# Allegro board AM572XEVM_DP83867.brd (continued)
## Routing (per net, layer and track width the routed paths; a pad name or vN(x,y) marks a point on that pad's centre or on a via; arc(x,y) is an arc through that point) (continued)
DDR2_D27: length 24.5
  TOP w0.12: U11.L28 55.72,38.01 54.86,38.86 54.49,38.86 54.38,38.76 54.38,38.33 54.28,38.23 54.13,38.23 54.02,38.33 54.02,38.76 53.92,38.86 53.77,38.86 53.66,38.76 53.66,38.33 53.56,38.23 53.41,38.23 53.3,38.33 53.3,38.76 53.2,38.86 53.05,38.86 52.95,38.76 52.95,38.33 52.84,38.23 52.69,38.23 52.59,38.33 52.59,38.76 52.48,38.86 52.33,38.86 52.23,38.76 52.23,38.33 52.12,38.23 51.97,38.23 51.87,38.33 51.87,38.76 51.76,38.86 51.61,38.86 51.51,38.76 51.51,38.33 51.4,38.23 51.25,38.23 51.15,38.33 51.15,38.76 51.04,38.86 50.55,38.86 49.78,38.1 49.78,35.69 48.51,34.42 43.17,34.42 43.05,34.3 43.05,33.13 U26.F7
DDR2_D28: length 24.2
  TOP w0.12: U11.M23 v2(60.19,38.41) ; v2(44.18,31.2) U26.F8
  INT_L3 w0.094: v2(60.19,38.41) 60.19,38.62 59.82,38.99 59.82,39.24 59.56,39.5 47.98,39.5 46.14,37.65 46.14,37.46 45.83,37.16 45.64,37.16 45.34,36.85 45.34,36.66 45.13,36.45 44.93,36.45 44.58,36.1 44.58,31.6 v2(44.18,31.2)
DDR2_D29: length 23.9
  TOP w0.12: v2(42.58,36) U26.H3 ; U11.M24 v2(59.39,38.41)
  BOTTOM w0.12: v2(59.39,38.41) 58.99,38.01 53.63,38.01 49.66,34.04 49.37,34.04 49.27,34.14 49.27,34.18 49.16,34.29 49.01,34.29 48.91,34.18 48.91,34.14 48.8,34.04 48.65,34.04 48.55,34.14 48.55,34.18 48.44,34.29 48.29,34.29 48.19,34.18 48.19,34.14 48.08,34.04 47.93,34.04 47.83,34.14 47.83,34.18 47.72,34.29 47.57,34.29 47.47,34.18 47.47,34.14 47.36,34.04 47.21,34.04 47.11,34.14 47.11,34.18 47,34.29 46.85,34.29 46.75,34.18 46.75,34.14 46.64,34.04 46.49,34.04 46.39,34.14 46.39,34.18 46.28,34.29 46.13,34.29 46.03,34.18 46.03,34.14 45.92,34.04 45.77,34.04 45.67,34.14 45.67,34.18 45.56,34.29 45.41,34.29 45.31,34.18 45.31,34.14 45.2,34.04 45.05,34.04 44.95,34.14 44.95,34.18 44.84,34.29 44.7,34.29 44.59,34.18 44.59,34.14 44.48,34.04 44.34,34.04 44.23,34.14 44.23,34.18 44.12,34.29 43.98,34.29 43.87,34.18 43.87,34.14 43.77,34.04 43.62,34.04 43.51,34.14 43.51,34.18 43.41,34.29 43.26,34.29 43.15,34.18 43.15,34.14 43.05,34.04 42.8,34.04 42.58,34.25 v2(42.58,36)
DDR2_D30: length 24.6
  TOP w0.12: v2(44.18,36.8) U26.F2 ; U11.M25 v2(58.59,38.41)
  BOTTOM w0.12: v2(44.18,36.8) 43.69,36.31 43.69,35.56 43.81,35.43 49.66,35.43 50.04,35.81 50.04,38.69 50.16,38.81 50.99,38.81 51.1,38.91 51.1,39.14 51.2,39.24 51.35,39.24 51.46,39.14 51.46,38.91 51.56,38.81 51.71,38.81 51.82,38.91 51.82,39.14 51.92,39.24 52.07,39.24 52.18,39.14 52.18,38.91 52.28,38.81 52.43,38.81 52.54,38.91 52.54,39.14 52.64,39.24 52.79,39.24 52.9,39.14 52.9,38.91 53,38.81 53.15,38.81 53.25,38.91 53.25,39.14 53.36,39.24 53.51,39.24 53.61,39.14 53.61,38.91 53.72,38.81 53.87,38.81 53.97,38.91 53.97,39.14 54.08,39.24 54.23,39.24 54.33,39.14 54.33,38.91 54.44,38.81 54.59,38.81 54.69,38.91 54.69,39.14 54.8,39.24 54.95,39.24 55.05,39.14 55.05,38.91 55.16,38.81 58.19,38.81 v2(58.59,38.41)
DDR2_D31: length 24.5
  TOP w0.12: U11.M26 v2(57.79,38.41) ; v2(43.38,36.8) U26.G2
  BOTTOM w0.12: v2(43.38,36.8) 43.38,34.79 43.5,34.67 43.75,34.67 43.86,34.78 43.86,34.95 43.96,35.05 44.11,35.05 44.21,34.95 44.21,34.78 44.32,34.67 44.47,34.67 44.57,34.78 44.57,34.95 44.68,35.05 44.83,35.05 44.93,34.95 44.93,34.78 45.04,34.67 45.19,34.67 45.29,34.78 45.29,34.95 45.4,35.05 45.55,35.05 45.65,34.95 45.65,34.78 45.76,34.67 45.91,34.67 46.01,34.78 46.01,34.95 46.12,35.05 46.27,35.05 46.37,34.95 46.37,34.78 46.48,34.67 46.63,34.67 46.73,34.78 46.73,34.95 46.84,35.05 46.99,35.05 47.09,34.95 47.09,34.78 47.2,34.67 47.35,34.67 47.45,34.78 47.45,34.95 47.56,35.05 47.71,35.05 47.81,34.95 47.81,34.78 47.92,34.67 48.07,34.67 48.17,34.78 48.17,34.95 48.28,35.05 48.43,35.05 48.53,34.95 48.53,34.78 48.64,34.67 48.79,34.67 48.89,34.78 48.89,34.95 49,35.05 49.14,35.05 49.25,34.95 49.25,34.78 49.36,34.67 49.78,34.67 50.54,35.42 50.54,37.45 51.49,38.41 v2(57.79,38.41)
DDR2_DQM0: length 20.1
  TOP w0.12: v1(50.29,28.96) 50.93,28.32 50.93,27.68 51.05,27.56 51.57,27.56 51.69,27.68 51.69,31.75 53.94,34.01 56.37,34.01 U11.F28 ; v2(45.78,24.8) U25.D3
  SIG_L10 w0.094: v1(50.29,28.96) 48.26,28.96 46.23,26.92 46.23,25.25 v2(45.78,24.8)
DDR2_DQM1: length 28.8
  TOP w0.12: v2(44.98,20.8) U25.E7 ; U11.G24 v2(59.39,34.41)
  INT_L3 w0.094: v2(44.98,20.8) 45.34,20.45 45.34,19.81 45.59,19.56 49.28,19.56 49.76,20.05 49.76,20.16 49.63,20.3 49.63,20.42 49.71,20.5 49.83,20.5 49.96,20.36 50.08,20.36 50.16,20.44 50.16,20.56 50.03,20.7 50.03,20.82 50.11,20.9 50.22,20.9 50.36,20.76 50.48,20.76 50.56,20.84 50.56,20.96 50.42,21.1 50.42,21.21 50.51,21.3 50.62,21.3 50.76,21.16 50.88,21.16 50.96,21.24 50.96,21.36 50.82,21.5 50.82,21.61 50.91,21.7 51.02,21.7 51.16,21.56 51.28,21.56 51.56,21.84 51.56,25.53 56.9,30.86 57.91,30.86 58.17,31.11 58.17,31.37 58.42,31.62 58.76,31.62 59.01,31.88 59.01,32.16 59.28,32.43 59.61,32.43 59.81,32.63 59.81,33.98 v2(59.39,34.41)
DDR2_DQM2: length 21.1
  TOP w0.12: v2(44.98,36) U26.D3 ; U11.K23 v2(60.19,36.81)
  SIG_L5 w0.094: v2(60.19,36.81) 60.17,36.81 59.77,37.21 51.7,37.21 49.67,35.18 49.55,35.18 49.47,35.26 49.47,35.48 49.39,35.56 49.27,35.56 49.19,35.48 49.19,35.26 49.1,35.18 48.99,35.18 48.9,35.26 48.9,35.48 48.82,35.56 48.7,35.56 48.62,35.48 48.62,35.26 48.54,35.18 48.42,35.18 48.34,35.26 48.34,35.48 48.26,35.56 48.14,35.56 48.06,35.48 48.06,35.26 47.98,35.18 47.86,35.18 47.78,35.26 47.78,35.48 47.69,35.56 47.58,35.56 47.49,35.48 47.49,35.26 47.41,35.18 47.3,35.18 47.21,35.26 47.21,35.48 47.13,35.56 47.01,35.56 46.93,35.48 46.93,35.26 46.85,35.18 46.73,35.18 46.65,35.26 46.65,35.48 46.57,35.56 46.45,35.56 46.37,35.48 46.37,35.26 46.28,35.18 45.81,35.18 v2(44.98,36)
DDR2_DQM3: length 24
  TOP w0.12: U11.M22 v2(60.99,38.41) ; v2(44.98,32) U26.E7
  BOTTOM w0.12: v2(60.99,38.41) 60.99,38.38 60.59,37.98 60.59,37.44 60.35,37.21 58.92,37.21 58.55,36.83 54.86,36.83 54.74,36.7 54.74,35.69 54.61,35.56 52.71,35.56 49.66,32.51 49.2,32.51 49.09,32.41 49.09,32.11 48.98,32 48.84,32 48.73,32.11 48.73,32.41 48.62,32.51 47.78,32.51 47.68,32.41 47.68,32.11 47.57,32 47.42,32 47.32,32.11 47.32,32.41 47.21,32.51 47.06,32.51 46.96,32.41 46.96,32.11 46.85,32 46.7,32 46.6,32.11 46.6,32.41 46.49,32.51 46.35,32.51 46.24,32.41 46.24,32.11 46.13,32 45.99,32 45.88,32.11 45.88,32.41 45.77,32.51 45.1,32.51 44.98,32.39 v2(44.98,32)
DDR2_DQS0: length 20.1
  TOP w0.102: U25.C7 46.48,21.2 46.61,21.34 46.61,21.72 47.24,22.35 47.75,22.35 49.53,24.13 49.53,30.73 53.55,34.75 56.53,34.75 U11.G28
DDR2_DQS1: length 28.4
  TOP w0.102: U25.F3 43.78,23.65 44.58,22.86 47.62,22.86 49.12,24.36 49.12,26.82 48.68,27.26 46.66,27.26 46.48,27.43 46.48,29.46 46.61,29.6 48.65,29.6 49.07,30.02 49.07,30.91 53.3,35.14 56.37,35.14 56.42,35.2 56.98,35.2 U11.H27
DDR2_DQS2: length 20.6
  TOP w0.102: U26.C7 46.58,32 47.12,32 47.34,32.23 47.34,32.61 47.52,32.79 48.11,32.79 48.62,32.28 49.3,32.28 49.66,32.64 49.66,32.9 49.8,33.05 50.06,33.05 50.46,33.45 50.46,33.83 50.65,34.02 51.03,34.02 51.44,34.42 51.44,34.88 51.52,34.97 51.77,34.97 52.07,35.27 52.07,35.69 51.77,35.98 51.52,35.98 51.44,36.07 51.44,36.45 52.09,37.11 52.32,37.11 52.41,37.02 52.41,36.24 52.71,35.94 53.13,35.94 53.43,36.24 53.43,37.02 53.52,37.11 53.64,37.11 53.73,37.02 53.73,36.24 54.03,35.94 54.45,35.94 54.75,36.24 54.75,37.02 54.84,37.11 55.09,37.11 55.41,36.8 56.98,36.8 U11.K27
DDR2_DQS3: length 24.2
  TOP w0.102: U11.M28 56.53,38.75 55.99,38.75 54.7,40.04 54.7,40.22 54.41,40.51 53.99,40.51 53.69,40.22 53.69,39.71 53.6,39.62 53.47,39.62 53.38,39.71 53.38,40.22 53.09,40.51 52.67,40.51 52.37,40.22 52.37,39.71 52.28,39.62 52.15,39.62 52.06,39.71 52.06,40.22 51.77,40.51 51.34,40.51 51.05,40.22 51.05,39.71 50.96,39.62 50.83,39.62 50.74,39.71 50.74,40.22 50.44,40.51 50.02,40.51 49.05,39.54 49.05,36.09 48.11,35.15 43.44,35.15 43.34,35.26 43.34,35.78 43.25,35.87 43.25,36.07 43.35,36.17 43.52,36.17 43.78,35.9 U26.F3
DDR2_DQSN0: length 20.1
  TOP w0.102: U25.B7 46.96,21.22 46.96,21.57 47.39,22 47.9,22 49.89,23.98 49.89,30.58 53.7,34.4 56.98,34.4 U11.G27
DDR2_DQSN1: length 28.4
  TOP w0.102: U25.G3 43.35,24.77 43.78,24.77 43.79,24.76 43.93,24.76 44.14,24.55 44.14,23.8 44.72,23.22 47.47,23.22 48.77,24.51 48.77,26.67 48.54,26.9 46.51,26.9 46.13,27.28 46.13,29.61 46.47,29.95 48.5,29.95 48.71,30.17 48.71,31.06 53.16,35.5 56.22,35.5 56.28,35.55 56.53,35.55 U11.H28
DDR2_DQSN2: length 20.5
  TOP w0.102: U11.K28 56.53,37.15 55.55,37.15 55.24,37.47 54.69,37.47 54.39,37.17 54.39,36.39 54.3,36.3 54.18,36.3 54.09,36.39 54.09,37.17 53.79,37.47 53.37,37.47 53.07,37.17 53.07,36.39 52.98,36.3 52.86,36.3 52.77,36.39 52.77,37.17 52.47,37.47 51.94,37.47 51.08,36.6 51.08,35.93 51.38,35.63 51.63,35.63 51.71,35.54 51.71,35.41 51.63,35.32 51.38,35.32 51.08,35.03 51.08,34.57 50.88,34.37 50.5,34.37 50.1,33.97 50.1,33.59 49.91,33.4 49.66,33.4 49.3,33.05 49.3,32.79 49.15,32.64 48.77,32.64 48.26,33.15 46.18,33.15 46.08,33.05 46.08,32.87 46.18,32.77 46.88,32.77 46.98,32.66 U26.B7
DDR2_DQSN3: length 24.2
  TOP w0.102: U11.M27 56.98,38.4 55.84,38.4 54.35,39.89 54.35,40.07 54.26,40.16 54.13,40.16 54.04,40.07 54.04,39.57 53.75,39.27 53.33,39.27 53.03,39.57 53.03,40.07 52.94,40.16 52.81,40.16 52.72,40.07 52.72,39.57 52.43,39.27 52,39.27 51.71,39.57 51.71,40.07 51.62,40.16 51.49,40.16 51.4,40.07 51.4,39.57 51.1,39.27 50.68,39.27 50.39,39.57 50.39,40.07 50.3,40.16 50.17,40.16 49.4,39.39 49.4,35.95 48.25,34.8 43.29,34.8 42.98,35.11 U26.G3
DDR2_ODT0: length 48.4
  TOP w0.12: v2(40.18,26.4) U25.K1 ; v2(40.18,37.6) U26.K1 ; U11.R23 v2(60.19,41.61)
  INT_L3 w0.094: v2(40.18,26.4) 40.18,26.67 41.4,27.89 41.4,35 40.58,35.82 U26.K1 v2(40.18,37.6)
  SIG_L5 w0.094: v2(40.18,37.6) 40.18,37.64 40.64,38.1 42.41,38.1 42.49,38.18 42.49,38.4 42.57,38.48 42.69,38.48 42.77,38.4 42.77,38.18 42.85,38.1 42.97,38.1 43.05,38.18 43.05,38.4 43.14,38.48 43.25,38.48 43.34,38.4 43.34,38.18 43.42,38.1 43.53,38.1 43.62,38.18 43.62,38.4 43.7,38.48 43.82,38.48 43.9,38.4 43.9,38.18 43.98,38.1 44.1,38.1 44.18,38.18 44.18,38.4 44.26,38.48 44.38,38.48 44.46,38.4 44.46,38.18 44.55,38.1 44.66,38.1 44.75,38.18 44.75,38.4 44.83,38.48 44.94,38.48 45.03,38.4 45.03,38.18 45.11,38.1 45.23,38.1 45.31,38.18 45.31,38.4 45.39,38.48 45.51,38.48 45.59,38.4 45.59,38.18 45.67,38.1 45.79,38.1 45.87,38.18 45.87,38.4 45.96,38.48 46.07,38.48 46.15,38.4 46.15,38.18 46.24,38.1 46.35,38.1 46.44,38.18 46.44,38.4 46.52,38.48 46.64,38.48 46.72,38.4 46.72,38.18 46.8,38.1 46.92,38.1 47,38.18 47,38.4 47.08,38.48 47.2,38.48 47.28,38.4 47.28,38.18 47.37,38.1 47.48,38.1 47.56,38.18 47.56,38.4 47.65,38.48 47.76,38.48 47.85,38.4 47.85,38.18 47.93,38.1 48.05,38.1 48.13,38.18 48.13,38.4 48.21,38.48 48.33,38.48 48.41,38.4 48.41,38.18 48.49,38.1 48.61,38.1 48.69,38.18 48.69,38.4 48.78,38.48 48.89,38.48 48.97,38.4 48.97,38.18 49.06,38.1 49.17,38.1 49.26,38.18 49.26,38.4 49.34,38.48 49.46,38.48 49.54,38.4 49.54,38.18 49.62,38.1 49.74,38.1 49.82,38.18 49.82,38.4 49.9,38.48 50.02,38.48 50.1,38.4 50.1,38.18 50.18,38.1 50.3,38.1 50.38,38.18 50.38,38.4 50.47,38.48 50.58,38.48 50.67,38.4 50.67,38.18 50.75,38.1 50.87,38.1 50.95,38.18 50.95,38.4 51.03,38.48 51.15,38.48 51.23,38.4 51.23,38.18 51.31,38.1 51.43,38.1 51.51,38.18 51.51,38.4 51.59,38.48 51.71,38.48 51.79,38.4 51.79,38.18 51.88,38.1 51.99,38.1 52.08,38.18 52.08,38.4 52.16,38.48 52.28,38.48 52.36,38.4 52.36,38.18 52.44,38.1 52.56,38.1 52.64,38.18 52.64,38.4 52.72,38.48 52.84,38.48 52.92,38.4 52.92,38.18 53,38.1 53.12,38.1 53.2,38.18 53.2,38.4 53.29,38.48 53.4,38.48 53.49,38.4 53.49,38.18 53.57,38.1 54.23,38.1 55.71,39.58 59.54,39.58 59.81,39.85 59.81,41.23 v2(60.19,41.61)
  BOTTOM w0.12: R341.1 v2(40.18,26.4)
DDR2_RASN: length 48.2
  TOP w0.12: v2(40.98,24.8) U25.J3 ; U11.T23 v2(60.19,42.41) ; v2(40.98,36) U26.J3
  INT_L3 w0.094: v2(40.98,24.8) 40.58,25.2 40.58,26.57 40.82,26.8 40.82,26.8 41.78,27.76 41.78,35.2 v2(40.98,36)
  SIG_L8 w0.094: v2(40.98,36) 41.4,36.42 41.4,38.35 41.53,38.48 48.77,38.48 49.9,39.61 49.9,39.73 49.64,39.99 49.64,40.11 49.72,40.19 49.83,40.19 50.1,39.93 50.22,39.93 50.3,40.01 50.3,40.13 50.03,40.39 50.03,40.51 50.12,40.59 50.23,40.59 50.5,40.33 50.61,40.33 50.7,40.41 50.7,40.53 50.43,40.79 50.43,40.91 50.52,40.99 50.63,40.99 50.9,40.73 51.01,40.73 51.1,40.81 51.1,40.93 50.83,41.19 50.83,41.31 50.91,41.39 51.03,41.39 51.29,41.12 51.41,41.12 51.49,41.21 51.49,41.32 51.23,41.59 51.23,41.7 51.31,41.79 51.43,41.79 51.69,41.52 51.81,41.52 51.89,41.61 51.89,41.72 51.63,41.99 51.63,42.1 51.71,42.19 51.83,42.19 52.09,41.92 52.21,41.92 52.29,42 52.29,42.12 52.03,42.39 52.03,42.5 52.18,42.66 52.3,42.66 52.56,42.39 52.68,42.39 52.76,42.48 52.76,42.59 52.5,42.86 52.5,42.97 52.83,43.31 53.14,43.31 53.23,43.22 53.23,42.86 53.31,42.78 53.43,42.78 53.51,42.86 53.51,43.22 53.59,43.31 53.71,43.31 53.79,43.22 53.79,42.86 53.87,42.78 53.99,42.78 54.07,42.86 54.07,43.22 54.15,43.31 54.27,43.31 54.35,43.22 54.35,42.86 54.44,42.78 54.55,42.78 54.64,42.86 54.64,43.22 54.72,43.31 54.83,43.31 54.92,43.22 54.92,42.86 55,42.78 57.14,42.78 57.52,42.41 58.05,42.41 58.43,42.78 59.81,42.78 v2(60.19,42.41)
  BOTTOM w0.12: R279.1 v2(40.98,24.8)
DDR2_RST: length 48.4
  TOP w0.12: v2(35.38,36.8) U26.T2 ; U11.R24 v2(59.39,41.61) ; v2(35.38,25.6) U25.T2
  SIG_L5 w0.094: v2(35.38,25.6) 35.73,25.95 35.73,26.68 35.65,26.76 35.64,26.76 35.56,26.84 35.56,26.96 35.64,27.04 35.65,27.04 35.73,27.12 35.73,27.24 35.65,27.32 35.64,27.32 35.56,27.4 35.56,27.52 35.64,27.6 35.65,27.6 35.73,27.69 35.73,27.8 35.65,27.89 35.64,27.89 35.56,27.97 35.56,28.09 35.64,28.17 35.65,28.17 35.73,28.25 35.73,28.45 TP21.1 35.73,29.16 35.73,29.49 35.65,29.58 35.64,29.58 35.56,29.66 35.56,29.78 35.64,29.86 35.65,29.86 35.73,29.94 35.73,32.34 34.98,33.09 34.98,36.4 v2(35.38,36.8)
  SIG_L8 w0.094: v2(35.38,36.8) U26.T2 36.37,36.4 36.58,36.19 36.58,35.55 37.21,34.92 42.16,34.92 43.05,35.81 43.05,36.23 43.23,36.4 49.61,36.4 50.8,37.59 51.18,37.59 54.36,40.77 54.77,40.77 54.85,40.68 54.85,40.09 54.93,40.01 55.05,40.01 55.13,40.09 55.13,40.68 55.22,40.77 55.33,40.77 55.42,40.68 55.42,40.09 55.5,40.01 55.61,40.01 55.7,40.09 55.7,40.68 55.78,40.77 55.9,40.77 55.98,40.68 55.98,40.47 56.06,40.39 56.18,40.39 56.26,40.47 56.26,40.68 56.34,40.77 56.46,40.77 56.54,40.68 56.54,40.47 56.63,40.39 56.74,40.39 56.82,40.47 56.82,40.68 56.91,40.77 57.02,40.77 57.11,40.68 57.11,40.47 57.19,40.39 57.31,40.39 57.39,40.47 57.39,40.68 57.47,40.77 57.59,40.77 57.67,40.68 57.67,40.47 57.75,40.39 57.87,40.39 57.95,40.47 57.95,40.68 58.04,40.77 58.15,40.77 58.23,40.68 58.23,40.47 58.32,40.39 58.43,40.39 58.52,40.47 58.52,40.68 58.6,40.77 59.06,40.77 59.39,41.1 v2(59.39,41.61)
DDR2_WEN: length 48.5
  TOP w0.12: U11.U25 v2(58.59,43.21) ; v2(39.38,24.8) U25.L3 ; v2(39.38,36) U26.L3
  INT_L3 w0.094: v2(39.38,36) 39.38,35.5 40.13,34.75 40.13,33.48 38.99,32.33 38.99,32.18 38.98,32.17 38.98,29.85 39,29.83 39,28.97 38.98,28.95 38.98,25.44 38.99,25.43 38.99,25.2 v2(39.38,24.8)
  SIG_L8 w0.094: v2(58.59,43.21) 58.32,43.21 58.16,43.05 58.16,43.05 57.94,42.83 57.94,42.83 57.91,42.8 57.66,42.8 57.4,43.05 57.4,43.43 57.21,43.63 55.75,43.63 55.31,44.07 52.45,44.07 48.95,40.57 47.68,40.57 47.57,40.46 47.57,39.96 47.49,39.88 47.37,39.88 47.29,39.96 47.29,40.3 47.21,40.39 47.09,40.39 47.01,40.3 47.01,39.96 46.93,39.88 46.81,39.88 46.73,39.96 46.73,40.3 46.64,40.39 46.53,40.39 46.44,40.3 46.44,39.96 46.36,39.88 46.24,39.88 46.16,39.96 46.16,40.3 46.08,40.39 45.96,40.39 45.88,40.3 45.88,39.96 45.8,39.88 45.68,39.88 45.6,39.96 45.6,40.3 45.52,40.39 45.4,40.39 45.32,40.3 45.32,39.96 45.23,39.88 45.12,39.88 45.03,39.96 45.03,40.3 44.95,40.39 44.83,40.39 44.75,40.3 44.75,39.96 44.67,39.88 44.55,39.88 44.47,39.96 44.47,40.3 44.39,40.39 44.27,40.39 44.19,40.3 44.19,39.96 44.11,39.88 43.99,39.88 43.91,39.96 43.91,40.3 43.82,40.39 43.71,40.39 43.62,40.3 43.62,39.96 43.54,39.88 43.43,39.88 43.34,39.96 43.34,40.3 43.26,40.39 43.14,40.39 43.06,40.3 43.06,39.96 42.98,39.88 42.86,39.88 42.78,39.96 42.78,40.3 42.7,40.39 42.58,40.39 42.5,40.3 42.5,39.96 42.41,39.88 42.3,39.88 42.21,39.96 42.21,40.3 42.13,40.39 42.02,40.39 41.93,40.3 41.93,39.96 41.85,39.88 41.73,39.88 41.65,39.96 41.65,40.3 41.57,40.39 41.28,40.39 39.78,38.89 39.78,36.4 v2(39.38,36)
  BOTTOM w0.12: R343.1 v2(39.38,24.8)
DDR_VREF_OFFN: length 52.2
  TOP w0.12: U11.A22 v2(60.99,29.61)
  TOP w0.254: v1(25.78,17.65) 25.92,17.52 Q5.1 ; U27.7 v1(26.42,21.46) 25.99,21.46 R288.1
  SIG_L5 w0.254: v1(26.42,21.46) 26.42,18.29 v1(25.78,17.65)
  SIG_L8 w0.094: v2(60.99,29.61) 60.58,30.01 60.58,30.61 60.4,30.78 60.02,30.78 59.82,30.99 59.82,31.27 59.53,31.56 56.84,31.56 56.54,31.25 56.54,30.88 50.93,25.27 50.93,20.95 47.12,17.14 26.29,17.14 v1(25.78,17.65)
DDR_VREFSTL1: length 87.1
  TOP w0.12: U11.Y18 v2(64.19,45.61)
  TOP w0.254: v2(38.58,53.61) U23.M8 ; v2(42.58,60.01) U23.H1 ; v2(42.58,48.81) U24.H1 ; v2(38.58,42.41) U24.M8
  TOP w0.381: 33.91,42.41 v2(34.58,42.41) ; 33.91,42.41 33.91,52.93 v2(34.58,53.61) ; 33.91,42.41 33.91,32.26 32.89,31.24 32.89,25.65 32.26,25.02 26.23,25.02 24.93,23.72 R290.2
  SIG_L5 w0.381: 58.67,45.59 56.52,45.59 52.7,49.4 43.18,49.4 v2(42.58,48.81) 41.78,48.01 41.78,46.74 38.99,43.94 34.29,43.94 33.91,43.56 33.91,42.79 34.29,42.41 v2(34.58,42.41)
  BOTTOM w0.254: v2(38.58,53.61) 38.9,53.92 C275.1 ; v2(42.58,48.81) U24.H1 C278.1 ; v2(64.19,45.61) 64.5,45.29 C273.1 ; v2(38.58,42.41) 38.9,42.72 C276.1 ; C277.1 42.19,59.53 42.19,59.61
  BOTTOM w0.381: v2(34.58,53.61) 34.58,54.57 35.05,55.04 39.04,55.04 41.53,57.53 41.53,59.23 41.91,59.61 42.19,59.61 v2(42.58,60.01)
DDR_VREFSTL2: length 68.9
  TOP w0.12: U11.N22 v2(60.99,39.21)
  TOP w0.254: v2(42.58,37.6) U26.H1 ; v2(38.58,20) U25.M8 ; v2(42.58,26.4) U25.H1 ; v2(38.58,31.2) U26.M8
  TOP w0.381: R291.2 27.91,23.75 28.16,24 33.91,24 ; 33.91,24 33.91,25.6 ; 33.91,24 33.91,20.68 v2(34.58,20) ; v2(34.58,25.6) 33.91,25.6 ; 33.91,25.6 33.91,30.53 v2(34.58,31.2)
  SIG_L5 w0.381: 39.24,21.46 34.42,21.46 34.04,21.08 34.04,20.38 34.42,20 v2(34.58,20) ; 39.24,21.46 39.88,21.46 42.04,23.62 42.04,25.86 v2(42.58,26.4) ; 39.24,21.46 38.99,21.21
  BOTTOM w0.254: v2(38.58,31.2) 38.9,31.52 C282.1 ; C280.1 U25.H1 v2(42.58,26.4) ; v2(38.58,20) 38.9,20.31 C279.1 ; 42.19,37.21 U26.H1 C281.1
  BOTTOM w0.381: C274.2 56.05,40.81 55.63,40.39 50.67,40.39 49.91,39.62 44.6,39.62 v2(42.58,37.6) 42.19,37.21 41.91,37.21 41.53,36.83 41.53,35.18 38.99,32.64 35.05,32.64 34.58,32.17 v2(34.58,31.2)
DMA_EVT1: length 69.8
  TOP w0.12: U11.P7 v2(73.79,40.01)
  SIG_L10 w0.094: v1(115.82,78.25) 115.44,78.25 110.36,73.18 110.36,70.54 111.76,69.14 111.76,64.85 110.92,64.01 110.92,63.22 108.46,60.76 106.58,60.76 101.09,55.27 89.18,55.27 83.31,49.4 79.68,49.4 78.73,48.45 78.54,48.45 78.23,48.15 78.23,47.96 77.13,46.85 76.94,46.85 76.63,46.55 76.63,46.36 76.33,46.05 76.14,46.05 75.03,44.95 75.03,44.76 74.73,44.45 74.54,44.45 74.21,44.13 74.21,40.94 73.79,40.51 v2(73.79,40.01)
  BOTTOM w0.12: P16.35 v1(115.82,78.25)
DMA_EVT3: length 69.4
  TOP w0.12: U11.N6 v2(74.59,39.21)
  SIG_L10 w0.094: v1(119.13,73.45) 116.8,71.12 115.57,71.12 115.32,70.87 115.32,57.28 105.28,47.24 91.44,47.24 84.71,40.51 81.92,40.51 81.66,40.26 79.37,40.26 78.99,40.64 75.44,40.64 74.96,40.17 74.96,39.78 74.59,39.41 v2(74.59,39.21)
  BOTTOM w0.12: P16.11 v1(119.13,73.45)
DMA_EVT4: length 61.3
  TOP w0.12: U11.M4 v2(76.19,38.41)
  SIG_L8 w0.094: v2(76.19,38.41) 76.15,38.41 75.81,38.74 75.81,39.36 76.08,39.63 76.46,39.63 76.58,39.75 76.58,40.13 76.61,40.16 76.61,40.16 76.83,40.38 76.83,40.38 77.47,41.02 77.74,41.02 77.99,41.27 78.61,41.27 78.99,41.66 81.53,41.66 82.07,42.19 82.44,42.19 82.65,42.4 82.65,43.66 86.82,47.83 86.82,49.06 93.01,55.25 100.69,55.25 107.78,62.34 108.83,62.34 111.13,64.65 111.17,64.65 111.38,64.85 111.38,64.89 111.61,65.13 111.61,65.76 114.05,68.2 116.08,68.2 116.31,68.43 116.31,68.82 116.6,69.11 118.67,69.11 v1(119.13,68.65)
  BOTTOM w0.12: P16.17 v1(119.13,68.65)
EEWP: length 14.6
  BOTTOM w0.12: U8.7 53.47,80.64 51.6,78.77 R37.1 48.26,77.85 47.88,77.47 46.23,77.47 44.96,76.2 TP4.1
EHRPWM2_TRIPZONE_INPUT: length 54.8
  TOP w0.12: U11.F6 v2(74.59,33.61)
  SIG_L5 w0.094: v1(118.24,36.34) 117.71,35.81 115.19,35.81 110.62,40.39 106.3,40.39 105.79,40.89 100.08,40.89 99.19,40.01 87.38,40.01 86.74,39.37 79.12,39.37 78.91,39.58 78.43,39.58 78.21,39.36 78.21,39.09 77.94,38.83 77.68,38.83 77.41,38.56 77.41,38.29 77.14,38.03 76.88,38.03 76.61,37.76 76.61,37.49 76.34,37.23 76.08,37.23 75.81,36.96 75.81,36.69 75.54,36.43 75.28,36.43 75.01,36.16 75.01,35.89 74.74,35.63 74.48,35.63 74.21,35.36 74.21,33.98 v2(74.59,33.61)
  BOTTOM w0.12: P18.6 119.04,35.54 v1(118.24,36.34)
EHRPWM2A: length 88.4
  TOP w0.12: U11.AC5 v2(75.39,48.01)
  SIG_L5 w0.094: v2(75.39,48.01) 75.39,48.31 74.96,48.73 74.96,49.75 74.42,50.29 73.79,50.29 73.41,50.67 73.41,52.96 70.36,56.01 57.38,56.01 46.96,66.42 35.31,66.42 27.43,58.55 27.43,43.18 26.16,41.91 25.27,41.91 24.77,41.4 24.77,39.5 21.61,36.34 v1(21.34,36.34)
  BOTTOM w0.12: P17.5 v1(21.34,36.34)
EHRPWM2B: length 45.8
  TOP w0.12: U11.D3 v2(76.99,32.01)
  SIG_L5 w0.094: v2(76.99,32.01) 77.41,31.58 77.41,30.16 77.58,29.99 85.7,29.99 86.87,28.83 98.17,28.83 98.55,29.21 116.2,29.21 116.71,29.72 v1(116.71,29.94)
  BOTTOM w0.12: v1(116.71,29.94) 115.91,29.14 P18.44
EMAC[0]_RXC: length 39.8
  TOP w0.12: U11.U5 v2(75.39,43.21) ; v1(81.41,43.43) 81.41,46.2 82.83,47.62 82.83,49 85.67,51.84 85.67,52.23 85.57,52.34 85.35,52.34 85.24,52.44 85.24,52.59 85.35,52.7 85.57,52.7 85.67,52.8 85.67,52.95 85.57,53.06 85.35,53.06 85.24,53.16 85.24,53.31 85.35,53.42 85.57,53.42 85.67,53.52 85.67,54.25 87.05,55.63 88.24,55.63 88.46,55.84 88.46,55.99 88.21,56.24 88.21,56.39 88.32,56.49 88.47,56.49 88.71,56.25 88.86,56.25 88.96,56.35 88.96,56.5 88.72,56.74 88.72,56.89 88.83,57 88.97,57 89.22,56.75 89.37,56.75 90.07,57.45 90.07,58.39 90.17,58.5 90.37,58.5 90.47,58.6 90.47,58.75 90.37,58.86 90.17,58.86 90.07,58.96 90.07,59.33 90.4,59.66 91.19,59.66 91.41,59.44 91.41,59.05 91.56,58.91 91.85,58.91 92,59.07 U14.32
  GND_L9 w0.094: v2(75.39,43.21) 75.79,43.61 77.19,43.61 77.39,43.41 77.39,43.08 77.7,42.77 78.77,42.77 79.43,42.11 81.69,42.11 81.86,42.29 81.86,42.7 81.41,43.15 v1(81.41,43.43)
EMAC[0]_RXCTL: length 40.2
  TOP w0.12: U14.38 95.09,64.24 95.4,63.93 95.4,62.45 94.46,61.51 94.46,57.3 85.57,48.41 85.57,45.82 84.81,45.06 84.81,43.84 83.03,42.06 83.03,41.58 82.22,40.77 v1(81.41,40.77) ; U11.V5 v2(75.39,44.01)
  GND_L9 w0.094: v2(75.39,44.01) 74.98,43.6 74.98,41.48 75.29,41.17 81,41.17 v1(81.41,40.77)
EMAC[0]_RXD0: length 39.9
  TOP w0.12: U14.33 92.5,58.52 92.2,58.22 91.19,58.22 90.73,57.76 90.73,56.41 90.09,55.77 89.94,55.77 89.54,56.17 89.39,56.17 89.29,56.06 89.29,55.91 89.68,55.52 89.68,55.37 89.58,55.26 89.43,55.26 89.03,55.66 88.88,55.66 88.78,55.55 88.78,55.4 89.17,55.01 89.17,54.86 89.07,54.75 88.92,54.75 88.52,55.15 88.37,55.15 88.27,55.05 88.27,54.9 88.67,54.5 88.67,54.35 88.56,54.24 88.41,54.24 88.01,54.64 87.87,54.64 87.76,54.54 87.76,54.39 88.16,53.99 88.16,53.84 87.91,53.59 87.76,53.59 87.37,53.98 87.23,53.98 87.12,53.87 87.12,53.72 87.5,53.34 87.5,53.19 87.4,53.08 87.25,53.08 86.87,53.47 86.72,53.47 86.61,53.36 86.61,53.21 87,52.83 87,52.68 86.89,52.57 86.74,52.57 86.36,52.96 86.21,52.96 86.1,52.85 86.1,52.71 86.49,52.32 86.49,52.17 83.29,48.97 83.29,47.57 81.84,46.13 81.84,43.87 v1(82.27,43.43) ; U11.W2 v2(77.79,44.81)
  GND_L9 w0.094: v2(77.79,44.81) 77.79,44.87 78.13,45.21 80.8,45.21 82.27,43.74 v1(82.27,43.43)
EMAC[0]_RXD1: length 40.1
  TOP w0.12: v1(82.3,45.21) 83.74,46.66 83.74,49 85.95,51.2 86.1,51.2 86.21,51.08 86.36,51.08 86.47,51.19 86.47,51.34 86.35,51.46 86.35,51.6 86.46,51.71 86.61,51.71 86.72,51.59 86.87,51.59 86.98,51.7 86.98,51.85 86.86,51.96 86.86,52.11 86.97,52.22 87.11,52.22 87.23,52.1 87.38,52.1 87.49,52.21 87.49,52.35 87.37,52.47 87.37,52.62 87.47,52.73 87.62,52.73 87.74,52.61 87.89,52.61 88,52.71 88,52.86 87.88,52.98 87.88,53.13 87.98,53.24 88.13,53.24 88.25,53.12 88.4,53.12 88.5,53.22 88.5,53.37 88.39,53.49 88.39,53.64 88.49,53.74 88.64,53.74 88.76,53.63 88.91,53.63 89.01,53.73 89.01,53.88 88.89,54 88.89,54.15 89,54.25 89.15,54.25 89.27,54.14 89.42,54.14 89.52,54.24 89.52,54.39 89.4,54.51 89.4,54.66 89.51,54.76 89.66,54.76 89.78,54.64 89.92,54.64 90.03,54.75 90.03,54.9 89.91,55.02 89.91,55.16 90.02,55.27 90.17,55.27 90.28,55.15 90.43,55.15 90.54,55.26 90.54,55.41 90.42,55.52 90.42,55.67 90.53,55.78 90.67,55.78 90.79,55.66 90.94,55.66 91.11,55.83 91.11,57.38 91.49,57.76 92.46,57.76 93,58.31 U14.34 ; U11.Y2 v2(77.79,45.61)
  GND_L9 w0.094: v2(77.79,45.61) 78.16,45.97 79.34,45.97 79.43,46.06 79.43,46.7 79.49,46.77 79.62,46.77 79.71,46.68 79.71,46.06 79.79,45.97 79.91,45.97 79.99,46.06 79.99,46.83 80.07,46.91 80.19,46.91 80.27,46.83 80.27,46.06 80.35,45.97 80.47,45.97 80.55,46.06 80.55,46.83 80.64,46.91 80.75,46.91 80.83,46.83 80.83,46.06 80.92,45.97 81.03,45.97 81.12,46.06 81.12,46.83 81.2,46.91 81.32,46.91 81.4,46.83 81.4,45.47 81.66,45.21 v1(82.3,45.21)
EMAC[0]_RXD2: length 40
  TOP w0.12: v1(81.41,42.55) 81.86,43 82.65,43 82.78,43.13 82.78,43.58 82.88,43.69 83.38,43.69 83.49,43.79 83.49,43.94 83.38,44.04 82.88,44.04 82.78,44.15 82.78,45.01 84.3,46.53 84.3,49.07 84.94,49.71 85.78,49.71 85.95,49.88 85.95,50.03 85.78,50.2 85.78,50.35 85.89,50.45 86.04,50.45 86.2,50.29 86.35,50.29 92.02,55.95 92.02,56.1 91.52,56.6 91.52,56.75 91.63,56.86 91.78,56.86 92.28,56.36 92.42,56.36 92.53,56.46 92.53,56.61 92.03,57.11 92.03,57.26 92.14,57.36 92.29,57.36 92.78,56.87 92.93,56.87 93.5,57.43 93.5,62.99 U14.35 ; U11.V3 v2(76.99,44.01)
  GND_L9 w0.094: v1(81.41,42.55) 80.95,43 80.95,43.87 80.7,44.12 79.53,44.12 79.45,44.04 79.45,43.89 79.55,43.79 79.83,43.79 80.04,43.59 80.04,43.1 79.86,42.93 79.4,42.93 78.71,43.61 77.62,43.61 77.23,44.01 v2(76.99,44.01)
EMAC[0]_RXD3: length 39.7
  TOP w0.12: U14.36 93.98,62.97 93.98,57.38 85.14,48.54 85.14,48.1 85.04,47.99 84.74,47.99 84.63,47.89 84.63,47.74 84.74,47.63 85.04,47.63 85.14,47.53 85.14,47.38 85.04,47.27 84.74,47.27 84.63,47.17 84.63,47.02 84.74,46.91 85.04,46.91 85.14,46.81 85.14,46.01 84.9,45.77 84.75,45.77 84.46,46.06 84.32,46.06 84.21,45.96 84.21,45.81 84.5,45.52 84.5,45.37 84.32,45.2 83.56,45.2 83.46,45.09 83.46,44.78 83.58,44.66 84.32,44.66 84.43,44.55 84.43,44.17 82.8,42.55 v1(82.3,42.55) ; U11.V4 v2(76.19,44.01)
  GND_L9 w0.094: v1(82.3,42.55) 82.3,42.82 81.84,43.28 81.84,43.69 81.1,44.42 80.8,44.42 80.72,44.51 80.72,44.75 80.63,44.83 80.52,44.83 80.43,44.75 80.43,44.51 80.35,44.42 80.23,44.42 80.15,44.51 80.15,44.75 80.07,44.83 79.95,44.83 79.87,44.75 79.87,44.51 79.79,44.42 79.67,44.42 79.59,44.51 79.59,44.75 79.51,44.83 79.39,44.83 79.31,44.75 79.31,44.51 79.22,44.42 76.61,44.42 v2(76.19,44.01)
EMAC[0]_TXC: length 19
  TOP w0.12: U11.W9 v2(72.19,44.81) ; v1(80.39,43.43) 80.39,46.46 81.03,47.09 81.03,48.26 83.31,50.55 R85.1
  PWR_L6 w0.094: v1(80.39,43.43) 80.39,44.32 79.56,45.16 72.54,45.16 v2(72.19,44.81)
EMAC[0]_TXCTL: length 20.2
  TOP w0.12: U11.V9 v2(72.19,44.01) ; v1(80.39,42.55) 80.9,43.05 80.9,46.35 81.28,46.74 81.28,47.5 81.53,47.75 82.04,47.75 82.3,48.01 82.3,48.9 84.07,50.67 R84.1
  PWR_L6 w0.094: v2(72.19,44.01) 72.54,43.65 72.54,43.03 72.77,42.8 78.87,42.8 78.96,42.9 80.04,42.9 v1(80.39,42.55)
EMAC[0]_TXD0: length 15.6
  TOP w0.12: R86.1 82.55,50.29 80.67,48.41 80.67,47.29 79.93,46.56 79.93,42.98 v1(79.5,42.55) ; U11.U6 v2(74.59,43.21)
  BOTTOM w0.12: v1(79.5,42.55) 79.24,42.81 74.97,42.81 74.59,43.19 v2(74.59,43.21)
EMAC[0]_TXD1: length 13.5
  TOP w0.12: U11.V6 v2(74.59,44.01) ; R87.1 81.89,50.99 81.89,50.11 80.34,48.56 80.34,47.45 79.58,46.69 79.58,46.1 79.33,45.86 79.16,45.86 79.04,45.98 79.04,46.25 78.89,46.41 v2(78.59,46.41)
  GND_L9 w0.094: v2(74.59,44.01) 74.84,44.01 75.29,44.45 75.59,44.45 75.77,44.63 75.77,44.98 76,45.21 77.17,45.21 77.37,45.42 77.37,45.8 77.98,46.41 v2(78.59,46.41)
EMAC[0]_TXD2: length 12.8
  TOP w0.12: U11.U7 v2(73.79,43.21) ; R88.1 81.03,50.75 80.87,50.6 80.87,49.68 80.04,48.84 80.04,48.03 79.76,47.75 79.13,47.75 v2(78.59,47.21)
  GND_L9 w0.094: v2(73.79,43.21) 74.17,43.59 74.17,44.2 74.42,44.45 74.8,44.45 75.01,44.65 75.01,44.93 76.05,45.97 77.06,45.97 78.29,47.21 v2(78.59,47.21)
EMAC[0]_TXD3: length 11.4
  TOP w0.12: R89.1 79.65,50.48 79.65,49.07 v2(78.59,48.01) ; U11.V7 v2(73.79,44.01)
  GND_L9 w0.094: v2(78.59,48.01) 77.37,46.79 75.97,46.79 75.74,46.56 75.74,46.15 74.8,45.21 74.4,45.21 74.19,45.01 74.19,44.7 73.79,44.3 v2(73.79,44.01)
EMAC[1]_RXC: length 73.6
  TOP w0.12: v1(82.3,32.38) 82.3,32.89 84.86,35.46 84.86,37.49 85.84,38.47 85.84,38.62 85.68,38.77 85.68,38.92 85.79,39.03 85.94,39.03 86.09,38.87 86.24,38.87 86.35,38.98 86.35,39.13 86.19,39.28 86.19,39.43 86.3,39.54 86.45,39.54 86.6,39.38 86.75,39.38 86.86,39.49 86.86,39.64 86.7,39.79 86.7,39.94 86.81,40.05 86.96,40.05 87.11,39.89 87.26,39.89 87.37,40 87.37,40.14 87.21,40.3 87.21,40.45 87.32,40.55 87.47,40.55 87.62,40.4 87.77,40.4 88.37,41 88.37,47.65 88.83,48.11 88.98,48.11 89.29,47.81 89.44,47.81 89.54,47.91 89.54,48.06 89.23,48.37 89.23,48.52 89.34,48.62 89.49,48.62 89.8,48.31 89.94,48.31 90.05,48.42 90.05,48.57 89.74,48.88 89.74,49.03 89.85,49.13 90,49.13 90.3,48.82 90.45,48.82 90.56,48.93 90.56,49.08 90.25,49.39 90.25,49.53 90.36,49.64 90.5,49.64 90.81,49.33 90.96,49.33 91.07,49.44 91.07,49.59 90.76,49.89 90.76,50.04 90.86,50.15 91.01,50.15 91.32,49.84 91.47,49.84 91.58,49.95 91.58,50.09 91.27,50.4 91.27,50.55 91.85,51.13 93.16,51.13 93.27,51.24 93.27,51.56 93.37,51.66 93.52,51.66 93.63,51.56 93.63,51.24 93.73,51.13 93.88,51.13 93.99,51.24 93.99,51.56 94.09,51.66 94.24,51.66 94.35,51.56 94.35,51.24 94.45,51.13 95,51.13 95.48,51.61 95.48,51.88 95.37,51.98 94.97,51.98 94.87,52.09 94.87,52.24 94.97,52.34 95.37,52.34 95.48,52.45 95.48,52.6 95.37,52.7 94.97,52.7 94.87,52.81 94.87,52.96 94.97,53.06 95.37,53.06 95.48,53.17 95.48,53.62 97.61,55.75 101.27,55.75 102.06,56.54 102.06,56.69 101.65,57.1 101.65,57.25 101.75,57.35 101.9,57.35 102.31,56.94 102.46,56.94 102.57,57.05 102.57,57.2 102.16,57.61 102.16,57.76 102.26,57.86 102.41,57.86 102.82,57.45 102.97,57.45 103.08,57.56 103.08,57.71 102.67,58.12 102.67,58.27 102.77,58.37 102.92,58.37 103.33,57.96 103.48,57.96 103.58,58.07 103.58,58.22 103.17,58.63 103.17,58.77 103.28,58.88 103.43,58.88 103.84,58.47 103.99,58.47 104.09,58.58 104.09,58.72 103.68,59.13 103.68,59.28 103.79,59.39 103.94,59.39 104.35,58.98 104.5,58.98 104.6,59.08 104.6,59.23 104.19,59.64 104.19,59.79 104.3,59.9 104.45,59.9 104.86,59.49 105,59.49 105.77,60.25 105.77,63.28 U15.32 ; U11.C5 v2(75.39,31.21)
  SIG_L10 w0.094: v1(82.3,32.38) 81.86,31.95 81.86,31.22 81.71,31.06 79.96,31.06 78.92,30.02 76.02,30.02 75.82,30.23 75.82,30.78 75.4,31.21 v2(75.39,31.21)
EMAC[1]_RXCTL: length 73.7
  TOP w0.12: U11.A3 v2(76.99,29.61) ; v1(74.3,26.16) 75.41,25.04 78.21,25.04 80.19,27.03 80.19,29.64 80.67,30.12 82.98,30.12 83.79,30.93 83.79,32.48 86.84,35.53 86.84,36.86 87.71,37.72 95.66,37.72 97.33,39.4 97.33,52.76 98.2,53.62 105.79,53.62 107.14,54.97 107.14,57.33 109.37,59.56 109.37,62.31 109.83,62.77 109.83,64.21 109.5,64.54 U15.38
  GND_L9 w0.094: v2(76.99,29.61) 74.73,27.35 74.73,26.59 v1(74.3,26.16)
EMAC[1]_RXD0: length 74.7
  TOP w0.12: U11.A4 v2(76.19,29.61) ; U15.33 v1(106.25,62.17) 106.25,61.74 106.53,61.47 106.53,59.94 106.14,59.56 105.97,59.56 105.8,59.73 105.65,59.73 105.55,59.62 105.55,59.47 105.71,59.31 105.71,59.16 105.61,59.05 105.46,59.05 105.29,59.22 105.14,59.22 105.04,59.11 105.04,58.97 105.21,58.8 105.21,58.65 105.1,58.54 104.95,58.54 104.78,58.71 104.63,58.71 104.53,58.61 104.53,58.46 104.7,58.29 104.7,58.14 104.59,58.03 104.44,58.03 104.27,58.2 104.13,58.2 104.02,58.1 104.02,57.95 104.19,57.78 104.19,57.63 104.08,57.53 103.93,57.53 103.77,57.69 103.62,57.69 103.51,57.59 103.51,57.44 103.68,57.27 103.68,57.12 103.57,57.02 103.43,57.02 103.26,57.19 103.11,57.19 103,57.08 103,56.93 103.17,56.76 103.17,56.61 103.07,56.51 102.92,56.51 102.75,56.68 102.6,56.68 102.49,56.57 102.49,56.42 102.66,56.25 102.66,56.1 101.88,55.32 97.84,55.32 95.86,53.34 95.86,50.19 95.48,49.81 92.99,49.81 92.66,49.48 92.66,48.97 92.94,48.69 93.34,48.69 93.45,48.8 93.45,49.02 93.55,49.12 93.7,49.12 93.81,49.02 93.81,48.8 93.91,48.69 94.06,48.69 94.17,48.8 94.17,49.02 94.27,49.12 94.42,49.12 94.53,49.02 94.53,48.8 94.63,48.69 94.78,48.69 94.88,48.8 94.88,49.02 94.99,49.12 95.14,49.12 95.24,49.02 95.24,48.8 95.35,48.69 95.61,48.69 95.86,48.44 95.86,39.93 94.95,39.01 86.92,39.01 85.34,37.44 85.34,35.53 82.73,32.92 82.73,31.93 v1(82.3,31.5)
  SIG_L10 w0.094: v2(76.19,29.61) 76.19,28.56 76.4,28.35 76.89,28.35 76.97,28.43 76.97,29.1 77.05,29.18 77.17,29.18 77.25,29.1 77.25,28.43 77.34,28.35 77.45,28.35 77.54,28.43 77.54,29.1 77.62,29.18 77.73,29.18 77.82,29.1 77.82,28.43 77.9,28.35 78.02,28.35 78.1,28.43 78.1,29.1 78.21,29.21 78.36,29.21 78.56,29.01 78.77,29.01 80.44,30.68 81.86,30.68 82.3,31.11 v1(82.3,31.5)
  BOTTOM w0.12: R461.2 106.27,62.15 v1(106.25,62.17)
EMAC[1]_RXD1: length 73.3
  TOP w0.12: U11.B5 v2(75.39,30.41) ; v1(76.96,26.16) 77.9,26.16 79.25,27.51 79.25,30.05 80.24,31.04 82.6,31.04 82.98,31.42 82.98,32.77 85.78,35.56 85.78,37.29 87.15,38.66 95.05,38.66 96.27,39.88 96.27,53.21 97.94,54.89 101.96,54.89 103.41,56.35 103.56,56.35 103.95,55.96 104.1,55.96 104.2,56.06 104.2,56.21 103.81,56.6 103.81,56.75 103.92,56.85 104.07,56.85 104.56,56.37 104.71,56.37 104.81,56.47 104.81,56.62 104.32,57.11 104.32,57.26 104.43,57.36 104.58,57.36 104.96,56.98 105.11,56.98 105.22,57.08 105.22,57.23 104.83,57.62 104.83,57.77 104.94,57.87 105.09,57.87 105.47,57.49 105.62,57.49 105.73,57.59 105.73,57.74 105.34,58.13 105.34,58.27 105.45,58.38 105.6,58.38 105.98,57.99 106.13,57.99 106.24,58.1 106.24,58.25 105.85,58.63 105.85,58.78 105.95,58.89 106.1,58.89 106.49,58.5 106.64,58.5 106.74,58.61 106.74,58.76 106.36,59.14 106.36,59.29 106.57,59.5 106.72,59.5 107.15,59.07 107.3,59.07 107.41,59.17 107.41,61.78 106.75,62.43 U15.34
  SIG_L10 w0.094: v1(76.96,26.16) 76.96,26.35 76.56,26.76 76.56,27.09 76.56,27.09 76.56,27.51 75.39,28.69 v2(75.39,30.41)
EMAC[1]_RXD2: length 73.5
  TOP w0.12: v1(76.07,26.16) 76.5,25.73 77.98,25.73 79.55,27.3 79.55,29.84 80.44,30.73 82.73,30.73 83.24,31.24 83.24,32.63 86.16,35.55 86.16,37.19 87.3,38.33 95.25,38.33 96.67,39.75 96.67,53.09 98.04,54.46 102.34,54.46 103,55.12 103.42,55.12 103.53,55.22 103.53,55.52 103.63,55.63 103.78,55.63 103.89,55.52 103.89,55.22 103.99,55.12 104.14,55.12 104.25,55.22 104.25,55.52 104.35,55.63 104.5,55.63 104.61,55.52 104.61,55.22 104.71,55.12 105.18,55.12 105.41,55.35 105.41,55.5 105.26,55.65 105.26,55.8 105.36,55.91 105.51,55.91 105.67,55.75 105.82,55.75 106.17,56.11 106.17,57.48 108.05,59.36 108.05,61.82 107.25,62.62 U15.35 ; U11.B4 v2(76.19,30.41)
  GND_L9 w0.094: v2(76.19,30.41) 76.19,30.52 76.5,30.84 77.93,30.84 78.18,30.58 78.18,29.13 77.93,28.88 77.93,28.51 77.99,28.45 77.99,28.34 77.91,28.25 77.79,28.25 77.73,28.31 77.61,28.31 77.53,28.23 77.53,28.11 77.59,28.05 77.59,27.94 77.51,27.85 77.39,27.85 77.33,27.91 77.22,27.91 77.13,27.83 77.13,27.72 77.19,27.65 77.19,27.54 77.11,27.45 77,27.45 76.93,27.52 76.82,27.52 76.56,27.25 76.56,26.64 v1(76.07,26.16)
EMAC[1]_RXD3: length 73.3
  TOP w0.12: U15.36 107.75,62.63 108.19,62.19 108.47,62.19 108.81,61.85 108.81,59.59 106.68,57.45 106.68,55.22 106.44,54.98 106.3,54.98 106.11,55.17 105.97,55.17 105.86,55.06 105.86,54.91 106.04,54.73 106.04,54.58 105.74,54.28 105.12,54.28 105.02,54.39 105.02,54.53 104.91,54.64 104.76,54.64 104.66,54.53 104.66,54.39 104.55,54.28 104.4,54.28 104.3,54.39 104.3,54.53 104.19,54.64 104.04,54.64 103.94,54.53 103.94,54.39 103.83,54.28 103.68,54.28 103.58,54.39 103.58,54.53 103.47,54.64 103.32,54.64 103.22,54.53 103.22,54.25 103,54.03 98.15,54.03 97,52.88 97,39.52 95.5,38.02 87.45,38.02 86.51,37.08 86.51,35.55 83.51,32.55 83.51,31.08 82.85,30.43 80.57,30.43 79.86,29.72 79.86,27.15 78.09,25.39 75.96,25.39 v1(75.18,26.16) ; U11.B3 v2(76.99,30.41)
  GND_L9 w0.094: v1(75.18,26.16) 75.21,26.16 75.59,26.54 75.59,27.3 76.6,28.31 76.71,28.31 76.8,28.22 76.92,28.22 77,28.31 77,28.42 76.91,28.51 76.91,28.63 77.39,29.11 77.39,30 v2(76.99,30.41)
EMAC[1]_TXC: length 11
  TOP w0.12: v1(81.41,32.38) 81.41,32.81 83.31,34.72 R112.1 ; U11.D5 v2(75.39,32.01)
  SIG_L10 w0.094: v1(81.41,32.38) 80.92,32.87 79.35,32.87 78.91,32.43 75.81,32.43 v2(75.39,32.01)
EMAC[1]_TXCTL: length 9.7
  TOP w0.12: R111.1 84.07,35.05 81.88,32.86 81.88,31.97 v1(81.41,31.5) ; U11.C2 v2(77.79,31.21)
  BOTTOM w0.12: v2(77.79,31.21) 78.19,31.61 78.75,31.61 79.06,31.91 80.99,31.91 v1(81.41,31.5)
EMAC[1]_TXD0: length 11.9
  TOP w0.12: U11.D6 v2(74.59,32.01) ; v1(80.52,31.5) 80.98,31.95 80.98,33.83 82.55,35.41 R113.1
  SIG_L10 w0.094: v1(80.52,31.5) 80.01,32 79.15,32 78.77,31.63 74.93,31.63 74.59,31.97 v2(74.59,32.01)
EMAC[1]_TXD1: length 8.5
  TOP w0.12: R114.1 81.79,35.23 80.62,34.06 80.62,32.49 v1(80.52,32.38) ; U11.B2 v2(77.79,30.41)
  SIG_L8 w0.094: v1(80.52,32.38) 80.11,31.98 80.11,31.22 78.88,29.98 78.22,29.98 77.8,30.41 v2(77.79,30.41)
EMAC[1]_TXD2: length 9
  TOP w0.12: v1(79.5,31.5) 80.01,32 80.01,32.64 80.31,32.94 80.31,34.34 81.03,35.05 R115.1 ; U11.C4 v2(76.19,31.21)
  SIG_L10 w0.094: v2(76.19,31.21) 76.61,30.78 78.79,30.78 v1(79.5,31.5)
EMAC[1]_TXD3: length 7.1
  TOP w0.12: U11.C3 v2(76.99,31.21) ; R118.1 80.26,35.05 80.04,34.82 80.04,33.17 79.76,32.89 79.76,32.64 v1(79.5,32.38)
  SIG_L8 w0.094: v1(79.5,32.38) 79.25,32.38 78.97,32.11 78.97,31.85 78.71,31.6 77.38,31.6 v2(76.99,31.21)
EMMC_VDD1.1: length 1.6
  TOP w0.12: U22.C2 95.07,41.32 v4(95.07,41.31)
  BOTTOM w0.12: v4(95.07,41.31) 95.11,41.27 C270.2
EMU0: length 22.8
  TOP w0.12: U11.G21 v2(61.79,34.41) ; R59.2 73.75,24.29 72.52,25.53 v1(72.52,26.16)
  SIG_L10 w0.094: v2(61.79,34.41) 61.84,34.41 62.23,34.8 63.53,34.8 63.81,34.52 63.81,34.23 64.01,34.03 66.8,34.03 67.31,33.52 67.31,29.97 68.45,28.83 70.74,28.83 72.11,27.45 72.11,26.69 72.52,26.29 v1(72.52,26.16)
  BOTTOM w0.12: v1(72.52,26.16) 73.03,25.65 73.03,24.3
EMU1: length 30.2
  TOP w0.12: U11.D24 v2(59.39,32.01) ; v1(73.03,20.83) 73.03,18.54 73.63,17.94 R62.2
  SIG_L8 w0.094: v1(73.03,20.83) 72.52,20.32 65.15,20.32 64.77,20.7 64.77,20.95 v1(64.13,21.59)
  GND_L9 w0.094: v1(64.13,21.59) 63.44,22.29 63.44,28.77 62.99,29.21 62.99,31.37 62.74,31.62 59.77,31.62 v2(59.39,32.01)
  BOTTOM w0.12: 73.03,18.88 v1(73.03,20.83)
EMU_RSTN: length 51.2
  INT_L3 w0.094: v1(78.23,22.35) 79.5,23.62 79.5,29.95 80.87,31.32 80.87,43.69 80.26,44.29 80.26,48.39 79.76,48.89 79.76,51.94 79.12,52.58 79.12,58.04 79.63,58.55 79.63,60.58 79.12,61.09 79.12,62.74 v1(79.76,63.37)
  BOTTOM w0.12: U10.2 80.01,63.12 v1(79.76,63.37) 79.54,63.59 R44.2 ; P4.15 74.3,22.61 74.55,22.35 v1(78.23,22.35)
ENET0_INTN: length 78.4
  TOP w0.12: U14.44 95.44,67.24 v1(95.66,67.46) ; U11.D26 v2(57.79,32.01)
  INT_L3 w0.094: v1(95.66,67.46) 95.28,67.08 95.28,60.3 91.54,56.57 91.54,49.73 91.95,49.33 91.95,48.29 90.4,46.74 90.4,41.99 92.84,39.55 92.84,37.47 v1(91.69,36.32)
  SIG_L8 w0.094: v2(57.79,32.01) 58.16,32.38 60.34,32.38 60.58,32.15 60.58,31.88 60.87,31.58 65.95,31.58 66.17,31.37 66.17,30.23 68.96,27.43 82.04,27.43 84.58,29.97 85.72,29.97 91.69,35.94 v1(91.69,36.32)
  BOTTOM w0.12: v1(95.66,67.46) 95.66,67.47 R468.2
ENET1_INTN: length 94.4
  TOP w0.12: U11.D28 v2(56.19,32.01) ; U15.44 109.19,67.54 v1(109.41,67.75)
  INT_L3 w0.094: v1(92.46,36.32) 93.09,36.96 93.09,39.88 90.93,42.04 90.93,46.61 92.3,47.98 92.3,49.48 91.92,49.86 91.92,56.26 95.89,60.22 95.89,63.96 96.24,64.31 100.91,64.31 101.75,65.15 101.75,66.29 102.74,67.28 108.28,67.28 108.75,67.75 v1(109.41,67.75)
  SIG_L8 w0.094: v2(56.19,32.01) 57.36,33.18 66.77,33.18 67.31,32.64 67.31,29.84 69.22,27.94 79.12,27.94 80.26,29.08 81.03,29.08 81.39,29.44 81.39,29.95 81.79,30.35 85.75,30.35 91.19,35.79 91.19,36.58 91.44,36.83 91.95,36.83 v1(92.46,36.32)
  BOTTOM w0.12: v1(109.41,67.75) 110.1,67.75 R469.2
ENET_PORZ: length 98.2
  TOP w0.12: U51.2 84.04,60.54 v1(84.05,60.53) ; U44.2 v1(109.32,53.52)
  INT_L3 w0.094: v1(89.15,27.18) 88.01,28.32 88.01,35.31 87.48,35.84 87.48,54.94 84.05,58.37 v1(84.05,60.53)
  SIG_L8 w0.094: v1(61.21,26.92) 63.39,24.74 86.74,24.74 86.74,24.77 v1(89.15,27.18)
  BOTTOM w0.12: R39.2 v1(61.21,26.92) 61.21,26.16 61.59,25.78 R40.2 ; v1(109.32,53.52) 105.21,57.63 86.44,57.63 84.05,60.02 v1(84.05,60.53)
ESATA_R+: length 1.5
  BOTTOM w0.102: C420.1 79.58,95.39 79.58,95.86 80.01,96.29 P6.10
ESATA_R-: length 1.5
  BOTTOM w0.102: C418.1 79.1,95.39 79.1,95.83 78.74,96.19 P6.9
ESATA_T+: length 8.7
  BOTTOM w0.102: P6.6 75.39,95.99 75.39,92.3 77.61,90.08 77.61,89.26 C416.2
ESATA_T-: length 8.7
  BOTTOM w0.102: C417.1 77.97,89.26 77.97,90.23 75.74,92.45 75.74,95.99 P6.7
ETH0_1V0: length 13.4
  TOP w0.254: U14.42 95.63,66.24 95.99,65.89 95.99,65.51 96.34,65.15 C519.1 96.72,65.59 v1(96.55,65.76) ; U14.24 86.54,63.74 C522.1 86.54,63.26 v1(86.67,63.12) ; v1(86.84,72.24) v1(87.43,72.24) 87.1,72.57 R471.2 ; v1(90.83,61.19) C520.1 91.31,61.46 91.51,61.66 91.51,62.99 U14.31 ; C518.1 91.5,71.79 v1(91.5,71.21) U14.6
  BOTTOM w0.254: v1(96.55,65.76) 96.55,65.75 C567.1 ; C569.1 86.71,63.16 v1(86.67,63.12) ; C568.1 90.87,61.23 v1(90.83,61.19) ; C566.1 91.52,71.22 v1(91.5,71.21)
ETH0_2V5: length 6.4
  TOP w0.254: C527.1 93,71.79 v1(93,71.21) U14.3 ; C526.1 90,71.78 v1(90,71.21) U14.9 ; R472.2 85.32,73.13 85.06,73.38 v1(84.45,73.38) v1(84.45,72.77)
  BOTTOM w0.254: C571.1 93.01,71.22 v1(93,71.21) ; v1(90,71.21) 90.02,71.22 C570.1
ETH0_3V3: length 14.1
  TOP w0.254: v1(96.55,63.78) 96.72,63.95 C512.1 96.24,64.39 95.55,65.07 95.55,65.48 95.29,65.74 U14.41 ; U14.19 87.33,66.24 86.88,65.8 86.88,65.59 C510.1 86.55,64.78 v1(86.69,64.64) ; v1(89.55,60.74) C511.1 90.25,60.9 90.25,61.45 91,62.2 U14.30
  BOTTOM w0.254: 86.7,64.63 v1(86.69,64.64) 86.71,64.66 C563.1 86.71,65.6 R442.1 ; v1(95.61,70.15) 96.49,69.27 R468.1 ; v1(96.55,63.78) 96.55,63.79 C565.1 ; C564.1 90.06,60.78 89.59,60.78 v1(89.55,60.74)
  vias: v1(96.95,62.84) v1(96.98,62.18) v1(97.54,62.84)
ETH0_LED0_YEL_LINK: length 48.1
  TOP w0.12: U14.47 95.14,68.74 v1(95.63,69.24)
  SIG_L5 w0.094: P5.27 103.76,101.09 100.61,101.09 96.37,96.85 93.8,96.85 93.24,96.29 93.24,92.76 94.97,91.03 94.97,87.76 93.12,85.9 93.12,78.61 97.05,74.68 97.05,70.28 96.01,69.24 v1(95.63,69.24)
ETH0_LED2_GRN_ACTIV: length 44.5
  TOP w0.12: U14.45 95.28,67.74 95.45,67.92 95.45,68.07 v1(95.66,68.28)
  SIG_L5 w0.094: v1(95.66,68.28) 95.12,68.81 95.12,69.52 95.38,69.77 95.89,69.77 96.55,70.43 96.55,74.47 92.58,78.44 92.58,86.11 94.16,87.68 94.16,90.65 92.43,92.38 92.43,96.55 93.27,97.38 95.68,97.38 97.41,99.11 97.41,102.62 P5.29
ETH0_RBIAS: length 1.8
  TOP w0.12: U14.12 88.5,70.81 88.39,70.92 R440.2
ETH0_RESET: length 15.6
  TOP w0.12: v1(86.27,62.57) 85.11,62.57 84.69,62.99 U51.4 ; U14.43 95.65,66.74 v1(95.66,66.75)
  SIG_L5 w0.094: v1(95.66,66.75) 95.66,64.95 92.85,62.14 86.7,62.14 v1(86.27,62.57)
ETH0_TRCT[0]: length 1.6
  BOTTOM w0.12: P5.14 C590.1
ETH0_TRCT[1]: length 1.5
  BOTTOM w0.12: P5.22 103.34,81.73 103.35,81.72 C591.1
ETH0_TRCT[2]: length 1.5
  BOTTOM w0.12: P5.17 C592.1
ETH0_TRCT[3]: length 1.4
  BOTTOM w0.12: P5.25 97.32,81.73 97.33,81.72 C593.1
ETH0_TRD[0]N: length 26.7
  TOP w0.102: v3(93.51,70.76) 93.51,71.03 93.58,71.11 93.58,73.5 93.51,73.57 U47.9 93.55,74.03 93.55,74.81 U47.2 93.51,75.22 93.45,75.29 v1(93.45,75.56)
  TOP w0.12: v3(93.51,70.76) 93.51,70 U14.2
  INT_L3 w0.094: v1(93.45,75.56) 93.45,75.84 93.56,75.96 93.56,76.37 94.33,77.14 99.21,77.14 103.12,81.05 105.46,81.05 106.32,81.92 106.32,83.19 105.79,83.72 104.72,83.72 104.6,83.59 104.6,83.3 P5.21
  BOTTOM w0.102: v3(93.51,70.76) 93.51,70.76 C530.2
ETH0_TRD[0]P: length 26.8
  TOP w0.102: v1(94.08,75.56) 94.08,75.29 94.01,75.22 U47.1 93.98,74.81 93.98,74.03 U47.10 94.01,73.57 93.94,73.49 93.94,71.11 94.02,71.03 v3(94.02,70.76)
  TOP w0.12: v3(94.02,70.76) 94.02,70.01 U14.1
  INT_L3 w0.094: P5.15 104.34,84.83 105.05,84.12 105.96,84.12 106.72,83.35 106.72,81.75 105.63,80.65 103.28,80.65 99.37,76.74 94.5,76.74 93.96,76.21 93.96,75.96 94.08,75.84 v1(94.08,75.56)
  BOTTOM w0.102: C529.2 94.02,70.76 v3(94.02,70.76)
ETH0_TRD[1]N: length 26.6
  TOP w0.102: P5.16 102.34,84.33 102.01,84 100.66,84 100.15,83.49 100.15,80.95 100.84,80.27 100.84,78.08 99.11,76.35 95.71,76.35 94.67,77.39 92.68,77.39 92.09,76.8 92.09,75.37 92.01,75.3 U47.5 92.05,74.81 92.05,74.03 U47.6 92.01,73.57 92.08,73.5 92.08,71.1 92.01,71.03 v3(92.01,70.76)
  TOP w0.12: U14.5 92.01,70 v3(92.01,70.76)
  BOTTOM w0.102: C531.2 92.02,70.76 v3(92.01,70.76)
ETH0_TRD[1]P: length 26.6
  TOP w0.102: P5.23 101.89,83.11 102.18,83.11 102.31,83.24 102.31,83.49 102.16,83.64 100.81,83.64 100.51,83.34 100.51,81.1 101.19,80.42 101.19,77.93 99.26,76 95.56,76 94.52,77.04 92.83,77.04 92.44,76.65 92.44,75.37 92.51,75.3 U47.4 92.48,74.81 92.48,74.03 U47.7 92.51,73.57 92.44,73.49 92.44,71.11 92.52,71.03 v3(92.52,70.76)
  TOP w0.12: U14.4 92.52,70.01 v3(92.52,70.76)
  BOTTOM w0.102: C532.2 92.52,70.76 v3(92.52,70.76)
ETH0_TRD[2]N: length 26.4
  TOP w0.102: v1(90.45,75.56) 90.45,75.29 90.52,75.22 U48.2 90.55,74.81 90.55,74.03 U48.9 90.52,73.54 90.59,73.47 90.59,73.33 90.58,73.32 90.58,71.1 90.51,71.03 v3(90.51,70.76)
  TOP w0.12: v3(90.51,70.76) 90.51,70 U14.8
  INT_L3 w0.094: v1(90.45,75.56) 90.45,75.84 90.57,75.96 90.57,76.84 89.79,77.62 89.79,79.1 91.71,81.03 99.64,81.03 100.23,81.61 100.23,83.21 99.61,83.82 98.88,83.82 98.63,83.57 98.63,83.25 P5.24
  BOTTOM w0.102: v3(90.51,70.76) 90.49,70.75 C533.2
ETH0_TRD[2]P: length 26.4
  TOP w0.102: v3(91.02,70.76) 91.02,71.01 90.94,71.09 90.94,73.32 90.95,73.33 90.95,73.47 91.02,73.54 U48.10 90.98,74.03 90.98,74.81 U48.1 91.02,75.22 91.08,75.29 v1(91.08,75.56)
  TOP w0.12: v3(91.02,70.76) 91.02,70.01 U14.7
  INT_L3 w0.094: P5.18 99.19,84.22 99.78,84.22 100.63,83.37 100.63,81.45 99.81,80.63 91.88,80.63 90.19,78.94 90.19,77.79 90.97,77.01 90.97,75.96 91.08,75.84 v1(91.08,75.56)
  BOTTOM w0.102: v3(91.02,70.76) 91,70.75 C534.2
ETH0_TRD[3]N: length 26.4
  TOP w0.102: v3(89.01,70.76) 89.01,71.02 89.08,71.1 89.08,73.32 89.09,73.33 89.09,73.47 89.02,73.54 U48.6 89.02,74.03 89.05,74.07 89.05,74.81 U48.5 89.02,75.3 89.09,75.37 89.09,76.02 87.93,77.17 87.93,78.59 89.1,79.76 91.6,79.76 92.56,80.72 92.56,81.62 90.91,83.27 90.91,84.23 91.64,84.96 92.63,84.96 93.62,83.97 95.91,83.97 96.32,84.38 P5.19
  TOP w0.12: v3(89.01,70.76) 89.01,70 U14.11
  BOTTOM w0.102: C535.2 89.01,70.28 v3(89.01,70.76)
ETH0_TRD[3]P: length 26.3
  TOP w0.102: v3(89.52,70.76) 89.52,71.01 89.44,71.09 89.44,73.32 89.45,73.33 89.45,73.47 89.52,73.54 U48.7 89.48,74.03 89.48,74.81 U48.4 89.52,75.3 89.45,75.37 89.45,76.16 88.29,77.32 88.29,78.44 89.25,79.4 91.74,79.4 92.91,80.57 92.91,81.76 91.26,83.41 91.26,84.08 91.79,84.61 92.49,84.61 93.48,83.62 96.06,83.62 96.19,83.48 96.19,83.19 96.06,83.06 95.82,83.06 P5.26
  TOP w0.12: v3(89.52,70.76) 89.52,70.01 U14.10
  BOTTOM w0.102: v3(89.52,70.76) 89.52,70.28 C536.2
ETH0_XI: length 5.8
  TOP w0.12: Y5.2 85.68,66.83 86.02,67.17 86.02,68.06 86.33,68.38 v1(86.87,68.38) 87,68.24 U14.15
  BOTTOM w0.12: C217.2 85.74,68.38 v1(86.87,68.38)
ETH0_XO: length 5.4
  TOP w0.12: R479.1 v1(86.64,70.89) 84.61,70.89 Y5.1
  BOTTOM w0.12: C218.2 86.16,69.14 86.64,69.62 v1(86.64,70.89)
ETH1_1V0: length 11.7
  TOP w0.254: U15.31 105.26,63.28 105.26,61.95 105.06,61.75 105.06,61.48 105.05,61.48 ; 105.05,61.48 C549.1 ; 105.05,61.48 v1(104.58,61.48) ; C551.1 105.25,72.1 v1(105.25,71.5) U15.6 ; v1(100.27,63.41) 100.13,63.55 C550.1 100.14,64.04 U15.24 ; v1(110.11,67.03) 110.25,66.89 C547.1 109.63,66.4 109.49,66.54 U15.42
  TOP w0.381: 111.66,72.9 R473.2
  BOTTOM w0.254: v1(105.25,71.5) 105.26,71.5 C578.1 ; v1(110.11,67.03) 110.11,66.41 C575.1 ; C576.1 100.3,63.44 v1(100.27,63.41) ; C577.1 105.07,61.48 v1(104.58,61.48)
  vias: v1(111.25,72.47) v1(112.09,72.47)
ETH1_2V5: length 5.2
  TOP w0.254: U15.3 v1(106.75,71.5) 106.75,72.1 C555.1 ; C556.1 103.76,71.5 v1(103.75,71.5) U15.9
  TOP w0.381: 109.58,72.9 R475.2
  BOTTOM w0.254: C580.1 106.76,71.5 v1(106.75,71.5) ; C579.1 103.76,71.5 v1(103.75,71.5)
  vias: v1(109.19,72.47) v1(110.01,72.47)
ETH1_3V3: length 15.5
  TOP w0.254: 111.23,62.1 110.79,62.1 v1(110.69,62) ; 111.23,62.1 v1(111.33,62) 111.02,61.7 R474.2 ; 111.23,62.1 111.02,62.31 v1(111.02,62.51) ; v1(103.36,61.04) C562.1 104,61.21 104,61.74 104.75,62.49 U15.30 ; v1(110.11,65) 110.25,65.14 C561.1 109.55,65.66 109.17,66.04 U15.41 ; v1(100.27,64.91) 100.13,65.05 C560.1 100.13,65.59 101.08,66.54 U15.19
  BOTTOM w0.254: v1(100.27,64.91) 100.3,64.94 C572.1 ; v1(108.38,62.81) 108.38,62.41 108.13,62.15 R461.1 ; R469.1 110.11,69.82 v1(109.37,70.56) ; C573.1 110.09,65.02 v1(110.11,65) ; C574.1 103.47,61.16 v1(103.36,61.04)
ETH1_LED0_YEL_LINK: length 11.8
  TOP w0.12: U15.47 108.89,69.04 v1(109.38,69.53)
  SIG_L5 w0.094: v1(109.38,69.53) 108.71,70.2 108.71,75.79 105.79,78.71 P5.31
ETH1_LED2_GRN_ACTIV: length 21.1
  TOP w0.12: v1(109.41,68.57) 109.2,68.36 109.2,68.21 109.03,68.04 U15.45
  SIG_L5 w0.094: P5.33 97.43,78.71 97.43,76.3 99.09,74.65 107.11,74.65 108.25,73.51 108.25,69.72 109.41,68.57 v1(109.41,68.57)
ETH1_RBIAS: length 1.8
  TOP w0.12: U15.12 102.25,70.95 102.16,71.04 R441.2
ETH1_RESET: length 12.8
  TOP w0.12: U44.4 v1(110.68,56.37) ; v1(109.41,67.04) 109.4,67.04 U15.43
  INT_L3 w0.094: v1(110.68,56.37) 110.68,56.78 110.21,57.25 110.21,64.08 109.41,64.89 v1(109.41,67.04)
ETH1_TRCT[0]: length 1.5
  BOTTOM w0.127: P5.7 C586.1
ETH1_TRCT[1]: length 1.5
  BOTTOM w0.127: C587.1 97.32,91.43 P5.12
ETH1_TRCT[2]: length 1.5
  BOTTOM w0.12: C588.1 P5.4
ETH1_TRCT[3]: length 1.5
  BOTTOM w0.127: C589.1 103.35,92.95 P5.9
ETH1_TRD[0]N: length 44.2
  TOP w0.102: v3(107.26,71.06) 107.26,71.32 107.33,71.4 107.33,73.79 107.26,73.87 U49.9 107.29,74.31 107.29,75.09 U49.2 107.26,75.58 107.33,75.65 107.33,76.19 108.92,77.77 108.92,85.83 106.65,88.09 106.65,90.81 107.57,91.72 107.57,95.89 106.58,96.88 98.27,96.88 97.49,96.09 97.49,94.57 96.92,94.01 95.91,94.01 95.69,94.23 95.47,94.23 95.31,94.07 P5.13
  TOP w0.12: v3(107.26,71.06) 107.26,70.29 U15.2
  BOTTOM w0.102: C537.2 107.26,71.05 v3(107.26,71.06)
ETH1_TRD[0]P: length 44.3
  TOP w0.102: P5.6 95.81,95 95.81,94.61 95.84,94.58 96.06,94.36 96.77,94.36 97.13,94.72 97.13,96.24 98.13,97.23 106.73,97.23 107.92,96.03 107.92,91.57 107.01,90.66 107.01,88.23 109.27,85.97 109.27,77.63 107.68,76.04 107.68,75.65 107.76,75.58 U49.1 107.72,75.09 107.72,74.31 U49.10 107.77,74.27 107.77,73.86 107.69,73.78 107.69,71.4 107.77,71.33 v3(107.77,71.06)
  TOP w0.12: U15.1 107.77,70.3 v3(107.77,71.06)
  BOTTOM w0.102: v3(107.77,71.06) 107.77,71.05 C544.2
